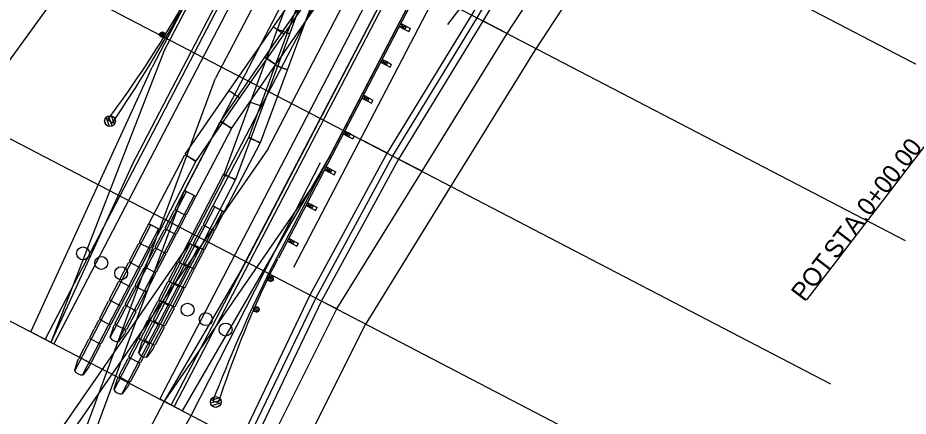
# Model space of a CAD drawing. Extents: x 2034057 to 2035954, y 247386 to 249135.
# Drawn here: x 2034166.1 to 2034303.8, y 247727.3 to 247789 of the extents above; entities that cross this region are included whole.
import ezdxf

# ---------------------------------------------------------------- set-up
doc = ezdxf.new("R2010")
doc.units = 0
for name, color, linetype in [('_CIVIL_CONSTRUCTION', 7, 'Continuous'), ('Default', 7, 'Continuous'), ('DR_X_Storm_Sewer', 7, 'Continuous'), ('DR_X_Text', 7, 'Continuous'), ('DV_X_Property_Line', 7, 'Continuous'), ('PV_X_Driveway', 7, 'Continuous'), ('RD_X_GR_Lt', 7, 'Continuous'), ('RS_Raster1', 7, 'Continuous'), ('RW_X_CL_100_Stations', 7, 'Continuous'), ('RW_X_Esmt_SH', 7, 'Continuous'), ('SC_Scratch1', 7, 'Continuous'), ('SN_X_Public', 7, 'Continuous'), ('SV_Control_Point', 7, 'Continuous'), ('SV_P_Mon_Cells_Set', 7, 'Continuous'), ('SV_X_Break_Lines', 7, 'Continuous'), ('XS_X_Ground_Line', 7, 'Continuous')]:
    doc.layers.add(name, color=color, linetype=linetype)

msp = doc.modelspace()

# ---------------------------------------------------------------- linework, layer by layer
at = {"layer": '_CIVIL_CONSTRUCTION'}
for p, q in [((2034285.21, 247856.53), (2034232.55, 247787.93)), ((2034340.74, 247813.92), (2034288.09, 247745.31))]:
    msp.add_line(p, q, dxfattribs=at)
at = {"layer": 'Default'}
for p, q in [((2034137.53, 247869), (2034314.92, 247776.64)), ((2034125.98, 247846.83), (2034303.38, 247754.47)), ((2034114.43, 247824.66), (2034291.83, 247732.29)), ((2034102.89, 247802.48), (2034280.28, 247710.12)), ((2034091.34, 247780.31), (2034268.74, 247687.94))]:
    msp.add_line(p, q, dxfattribs=at)
at = {"layer": 'DR_X_Storm_Sewer'}
for p, q in [((2034208.79, 247750.36), (2034247.98, 247825.63)), ((2034241.77, 247786.54), (2034238.03, 247788.49)), ((2034219.1, 247770.16), (2034223.2, 247768.03)), ((2034228.62, 247765.2), (2034224.97, 247767.1)), ((2034215.42, 247743.89), (2034213.05, 247745.12))]:
    msp.add_line(p, q, dxfattribs=at)
for points in [[(2034256.26, 247823.15), (2034236.29, 247789.47), (2034223.22, 247768.07), (2034211.27, 247746.04), (2034200.52, 247723.55), (2034200.47, 247723.49)], [(2034257.98, 247822.13), (2034238, 247788.44), (2034224.95, 247767.07), (2034213.06, 247745.13), (2034202.26, 247722.56)], [(2034228.62, 247765.2), (2034241.77, 247786.54), (2034255.56, 247807.55), (2034261.45, 247817.37)], [(2034204.23, 247721.53), (2034215.42, 247743.89), (2034228.62, 247765.2)]]:
    msp.add_lwpolyline(points, dxfattribs=at)
at = {"layer": 'DR_X_Text'}
msp.add_lwpolyline([(2034185.35, 247713.83), (2034192.91, 247727.42), (2034204.24, 247749.71), (2034212.91, 247766.55)], dxfattribs=at)
at = {"layer": 'DV_X_Property_Line'}
for p, q in [((2034235.31, 247874.38), (2034186.85, 247781.31)), ((2034262.59, 247860.18), (2034214.13, 247767.11)), ((2034168.07, 247740.36), (2034186.85, 247781.31)), ((2034191.57, 247728.12), (2034214.13, 247767.11)), ((2034168.07, 247740.36), (2034170.28, 247739.21)), ((2034189.8, 247729.05), (2034191.57, 247728.12))]:
    msp.add_line(p, q, dxfattribs=at)
at = {"layer": 'PV_X_Driveway'}
for p, q in [((2034183.71, 247766.07), (2034239.08, 247872.42)), ((2034247.06, 247868.27), (2034191.69, 247761.92)), ((2034183.71, 247766.07), (2034171.19, 247738.73)), ((2034191.69, 247761.92), (2034157.41, 247669.23)), ((2034184.77, 247737.07), (2034196.54, 247759.68)), ((2034197.72, 247759.06), (2034185.95, 247736.45)), ((2034194.78, 247757.02), (2034196.24, 247759.83)), ((2034198.02, 247758.91), (2034196.24, 247759.83)), ((2034196.56, 247756.1), (2034198.02, 247758.91)), ((2034193.24, 247754.07), (2034194.63, 247756.73)), ((2034194.85, 247756.8), (2034194.63, 247756.73)), ((2034194.78, 247757.02), (2034194.85, 247756.8)), ((2034196.33, 247756.03), (2034194.85, 247756.8)), ((2034195.02, 247753.14), (2034196.4, 247755.8)), ((2034196.56, 247756.1), (2034196.33, 247756.03)), ((2034196.33, 247756.03), (2034196.4, 247755.8)), ((2034191.7, 247751.11), (2034193.09, 247753.77)), ((2034193.31, 247753.84), (2034193.09, 247753.77)), ((2034193.24, 247754.07), (2034193.31, 247753.84)), ((2034194.79, 247753.07), (2034193.31, 247753.84)), ((2034193.48, 247750.19), (2034194.86, 247752.85)), ((2034195.02, 247753.14), (2034194.79, 247753.07)), ((2034194.79, 247753.07), (2034194.86, 247752.85)), ((2034190.16, 247748.15), (2034191.55, 247750.81)), ((2034191.77, 247750.88), (2034191.55, 247750.81)), ((2034191.7, 247751.11), (2034191.77, 247750.88)), ((2034193.25, 247750.11), (2034191.77, 247750.88)), ((2034191.94, 247747.23), (2034193.32, 247749.89)), ((2034193.48, 247750.19), (2034193.25, 247750.11)), ((2034193.25, 247750.11), (2034193.32, 247749.89)), ((2034190.16, 247748.15), (2034190.23, 247747.93)), ((2034188.62, 247745.2), (2034190.01, 247747.86)), ((2034190.23, 247747.93), (2034190.01, 247747.86)), ((2034191.71, 247747.16), (2034190.23, 247747.93)), ((2034190.4, 247744.27), (2034191.78, 247746.93)), ((2034191.94, 247747.23), (2034191.71, 247747.16)), ((2034191.71, 247747.16), (2034191.78, 247746.93)), ((2034187.08, 247742.24), (2034188.47, 247744.9)), ((2034188.69, 247744.97), (2034188.47, 247744.9)), ((2034188.62, 247745.2), (2034188.69, 247744.97)), ((2034190.17, 247744.2), (2034188.69, 247744.97)), ((2034190.24, 247743.98), (2034188.86, 247741.32)), ((2034190.4, 247744.27), (2034190.17, 247744.2)), ((2034190.17, 247744.2), (2034190.24, 247743.98)), ((2034185.55, 247739.28), (2034186.93, 247741.94)), ((2034187.16, 247742.01), (2034186.93, 247741.94)), ((2034187.08, 247742.24), (2034187.16, 247742.01)), ((2034188.63, 247741.24), (2034187.16, 247742.01)), ((2034188.86, 247741.32), (2034188.63, 247741.24)), ((2034188.63, 247741.24), (2034188.7, 247741.02)), ((2034188.7, 247741.02), (2034187.32, 247738.36)), ((2034185.19, 247738.6), (2034184.72, 247737.15)), ((2034185.19, 247738.6), (2034185.39, 247738.99)), ((2034185.62, 247739.06), (2034185.39, 247738.99)), ((2034185.55, 247739.28), (2034185.62, 247739.06)), ((2034187.09, 247738.29), (2034185.62, 247739.06)), ((2034187.32, 247738.36), (2034187.09, 247738.29)), ((2034186.96, 247737.68), (2034186.05, 247736.46)), ((2034187.17, 247738.06), (2034186.96, 247737.68)), ((2034187.09, 247738.29), (2034187.17, 247738.06))]:
    msp.add_line(p, q, dxfattribs=at)
for points in [[(2034207.78, 247780.92), (2034211.95, 247792.17), (2034210.07, 247792.87), (2034205.9, 247781.61)], [(2034203.61, 247769.67), (2034207.78, 247780.92), (2034205.9, 247781.61), (2034201.74, 247770.36)], [(2034198.02, 247758.91), (2034203.56, 247769.55), (2034201.79, 247770.47), (2034196.24, 247759.83)]]:
    msp.add_lwpolyline(points, close=True, dxfattribs=at)
for centre in [(2034176.16, 247752.49), (2034178.98, 247751.02), (2034182.06, 247749.42), (2034192.33, 247743.78), (2034195.15, 247742.31), (2034198.22, 247740.71)]:
    msp.add_circle(centre, 1, dxfattribs=at)
msp.add_arc((2034185.89, 247737.79), 1.34, 208.3199, 276.6713, dxfattribs=at)
at = {"layer": 'RD_X_GR_Lt'}
for p, q in [((2034204.76, 247768.61), (2034254.6, 247864.34)), ((2034212.74, 247764.45), (2034262.59, 247860.18)), ((2034204.76, 247768.61), (2034133.48, 247665.92)), ((2034212.74, 247764.45), (2034188.71, 247729.61)), ((2034180.38, 247739.46), (2034192.15, 247762.07)), ((2034190.39, 247759.41), (2034191.85, 247762.22)), ((2034193.63, 247761.3), (2034191.85, 247762.22)), ((2034193.33, 247761.45), (2034181.56, 247738.85)), ((2034192.16, 247758.49), (2034193.63, 247761.3)), ((2034188.85, 247756.46), (2034190.24, 247759.12)), ((2034190.46, 247759.19), (2034190.24, 247759.12)), ((2034190.39, 247759.41), (2034190.46, 247759.19)), ((2034191.94, 247758.42), (2034190.46, 247759.19)), ((2034190.62, 247755.53), (2034192.01, 247758.2)), ((2034192.16, 247758.49), (2034191.94, 247758.42)), ((2034191.94, 247758.42), (2034192.01, 247758.2)), ((2034188.85, 247756.46), (2034188.92, 247756.23)), ((2034187.31, 247753.5), (2034188.7, 247756.16)), ((2034188.92, 247756.23), (2034188.7, 247756.16)), ((2034190.4, 247755.46), (2034188.92, 247756.23)), ((2034189.09, 247752.58), (2034190.47, 247755.24)), ((2034190.62, 247755.53), (2034190.4, 247755.46)), ((2034190.4, 247755.46), (2034190.47, 247755.24)), ((2034187.31, 247753.5), (2034187.38, 247753.28)), ((2034185.77, 247750.54), (2034187.16, 247753.21)), ((2034187.38, 247753.28), (2034187.16, 247753.21)), ((2034188.86, 247752.51), (2034187.38, 247753.28)), ((2034187.55, 247749.62), (2034188.93, 247752.28)), ((2034189.09, 247752.58), (2034188.86, 247752.51)), ((2034188.86, 247752.51), (2034188.93, 247752.28)), ((2034184.23, 247747.59), (2034185.62, 247750.25)), ((2034185.84, 247750.32), (2034185.62, 247750.25)), ((2034185.77, 247750.54), (2034185.84, 247750.32)), ((2034187.32, 247749.55), (2034185.84, 247750.32)), ((2034187.55, 247749.62), (2034187.32, 247749.55)), ((2034187.32, 247749.55), (2034187.39, 247749.33)), ((2034186.01, 247746.66), (2034187.39, 247749.33)), ((2034182.69, 247744.63), (2034184.08, 247747.29)), ((2034184.3, 247747.36), (2034184.08, 247747.29)), ((2034184.23, 247747.59), (2034184.3, 247747.36)), ((2034185.78, 247746.59), (2034184.3, 247747.36)), ((2034186.01, 247746.66), (2034185.78, 247746.59)), ((2034185.78, 247746.59), (2034185.85, 247746.37)), ((2034185.85, 247746.37), (2034184.47, 247743.71)), ((2034181.15, 247741.68), (2034182.54, 247744.34)), ((2034182.76, 247744.41), (2034182.54, 247744.34)), ((2034182.69, 247744.63), (2034182.76, 247744.41)), ((2034184.24, 247743.64), (2034182.76, 247744.41)), ((2034184.31, 247743.41), (2034182.93, 247740.75)), ((2034184.47, 247743.71), (2034184.24, 247743.64)), ((2034184.24, 247743.64), (2034184.31, 247743.41)), ((2034180.8, 247740.99), (2034181, 247741.38)), ((2034181.22, 247741.45), (2034181, 247741.38)), ((2034181.15, 247741.68), (2034181.22, 247741.45)), ((2034182.7, 247740.68), (2034181.22, 247741.45)), ((2034180.8, 247740.99), (2034180.33, 247739.55)), ((2034182.57, 247740.07), (2034181.66, 247738.85)), ((2034182.77, 247740.46), (2034182.57, 247740.07)), ((2034182.93, 247740.75), (2034182.7, 247740.68)), ((2034182.7, 247740.68), (2034182.77, 247740.46))]:
    msp.add_line(p, q, dxfattribs=at)
for points in [[(2034212.76, 247791.57), (2034205.93, 247781.7), (2034204.29, 247782.84), (2034211.12, 247792.71)], [(2034205.93, 247781.7), (2034199.1, 247771.84), (2034197.46, 247772.97), (2034204.29, 247782.84)], [(2034199.17, 247771.94), (2034193.63, 247761.3), (2034191.85, 247762.22), (2034197.39, 247772.87)]]:
    msp.add_lwpolyline(points, close=True, dxfattribs=at)
msp.add_lwpolyline([(2034188.71, 247729.61), (2034177.8, 247708.67), (2034166.36, 247686.43), (2034157.41, 247669.23)], dxfattribs=at)
msp.add_arc((2034181.5, 247740.18), 1.34, 208.3199, 276.6713, dxfattribs=at)
at = {"layer": 'RS_Raster1'}
for p, q in [((2034188.68, 247783.74), (2034235.76, 247874.15)), ((2034243.74, 247870), (2034196.67, 247779.59)), ((2034206.26, 247787.17), (2034210.43, 247798.42)), ((2034208.14, 247786.48), (2034212.3, 247797.73)), ((2034202.09, 247775.92), (2034206.26, 247787.17)), ((2034206.26, 247787.17), (2034208.14, 247786.48)), ((2034206.26, 247787.17), (2034208.14, 247786.48)), ((2034203.97, 247775.22), (2034208.14, 247786.48)), ((2034188.68, 247783.74), (2034171.19, 247738.73)), ((2034151.87, 247658.6), (2034196.67, 247779.59)), ((2034197.92, 247764.66), (2034202.09, 247775.92)), ((2034202.09, 247775.92), (2034203.97, 247775.22)), ((2034202.09, 247775.92), (2034203.97, 247775.22)), ((2034199.8, 247763.97), (2034203.97, 247775.22)), ((2034192.43, 247754.14), (2034197.97, 247764.78)), ((2034197.92, 247764.66), (2034199.8, 247763.97)), ((2034197.97, 247764.78), (2034199.75, 247763.86)), ((2034194.21, 247753.21), (2034199.75, 247763.86)), ((2034180.96, 247731.37), (2034192.73, 247753.98)), ((2034190.97, 247751.33), (2034192.43, 247754.14)), ((2034192.43, 247754.14), (2034194.21, 247753.21)), ((2034194.21, 247753.21), (2034192.43, 247754.14)), ((2034193.91, 247753.37), (2034182.14, 247730.76)), ((2034192.74, 247750.4), (2034194.21, 247753.21)), ((2034189.43, 247748.37), (2034190.82, 247751.03)), ((2034191.04, 247751.1), (2034190.82, 247751.03)), ((2034190.97, 247751.33), (2034191.04, 247751.1)), ((2034192.52, 247750.33), (2034191.04, 247751.1)), ((2034191.21, 247747.45), (2034192.59, 247750.11)), ((2034192.74, 247750.4), (2034192.52, 247750.33)), ((2034192.52, 247750.33), (2034192.59, 247750.11)), ((2034187.89, 247745.41), (2034189.28, 247748.07)), ((2034189.5, 247748.15), (2034189.28, 247748.07)), ((2034189.43, 247748.37), (2034189.5, 247748.15)), ((2034190.98, 247747.38), (2034189.5, 247748.15)), ((2034189.67, 247744.49), (2034191.05, 247747.15)), ((2034191.21, 247747.45), (2034190.98, 247747.38)), ((2034190.98, 247747.38), (2034191.05, 247747.15)), ((2034187.89, 247745.41), (2034187.96, 247745.19)), ((2034186.35, 247742.46), (2034187.74, 247745.12)), ((2034187.96, 247745.19), (2034187.74, 247745.12)), ((2034189.44, 247744.42), (2034187.96, 247745.19)), ((2034188.13, 247741.53), (2034189.51, 247744.19)), ((2034189.67, 247744.49), (2034189.44, 247744.42)), ((2034189.44, 247744.42), (2034189.51, 247744.19)), ((2034184.81, 247739.5), (2034186.2, 247742.16)), ((2034186.42, 247742.23), (2034186.2, 247742.16)), ((2034186.35, 247742.46), (2034186.42, 247742.23)), ((2034187.9, 247741.46), (2034186.42, 247742.23)), ((2034186.59, 247738.58), (2034187.97, 247741.24)), ((2034188.13, 247741.53), (2034187.9, 247741.46)), ((2034187.9, 247741.46), (2034187.97, 247741.24)), ((2034183.27, 247736.54), (2034184.66, 247739.2)), ((2034184.88, 247739.28), (2034184.66, 247739.2)), ((2034184.81, 247739.5), (2034184.88, 247739.28)), ((2034186.36, 247738.51), (2034184.88, 247739.28)), ((2034186.59, 247738.58), (2034186.36, 247738.51)), ((2034186.36, 247738.51), (2034186.43, 247738.28)), ((2034186.43, 247738.28), (2034185.05, 247735.62)), ((2034181.73, 247733.59), (2034183.12, 247736.25)), ((2034183.34, 247736.32), (2034183.12, 247736.25)), ((2034183.27, 247736.54), (2034183.34, 247736.32)), ((2034184.82, 247735.55), (2034183.34, 247736.32)), ((2034185.05, 247735.62), (2034184.82, 247735.55)), ((2034184.89, 247735.32), (2034183.51, 247732.66)), ((2034184.82, 247735.55), (2034184.89, 247735.32)), ((2034181.38, 247732.9), (2034180.91, 247731.46)), ((2034181.38, 247732.9), (2034181.58, 247733.29)), ((2034181.81, 247733.36), (2034181.58, 247733.29)), ((2034181.73, 247733.59), (2034181.81, 247733.36)), ((2034183.28, 247732.59), (2034181.81, 247733.36)), ((2034183.15, 247731.98), (2034182.24, 247730.77)), ((2034183.35, 247732.37), (2034183.15, 247731.98)), ((2034183.51, 247732.66), (2034183.28, 247732.59)), ((2034183.28, 247732.59), (2034183.35, 247732.37))]:
    msp.add_line(p, q, dxfattribs=at)
msp.add_arc((2034182.08, 247732.09), 1.34, 208.3199, 276.6713, dxfattribs=at)
at = {"layer": 'RW_X_CL_100_Stations'}
msp.add_line((2034315.48, 247781.01), (2034288.09, 247745.31), dxfattribs=at)
at = {"layer": 'RW_X_Esmt_SH'}
for p, q in [((2034239.53, 247872.19), (2034170.28, 247739.21)), ((2034259.04, 247862.03), (2034189.8, 247729.05)), ((2034217.8, 247827.21), (2034171.62, 247738.51)), ((2034234.21, 247818.67), (2034188.02, 247729.97)), ((2034170.28, 247739.21), (2034171.62, 247738.51)), ((2034188.02, 247729.97), (2034189.8, 247729.05))]:
    msp.add_line(p, q, dxfattribs=at)
at = {"layer": 'SC_Scratch1'}
for p, q in [((2034251.06, 247866.19), (2034192.77, 247754.24)), ((2034200.75, 247750.08), (2034259.04, 247862.03)), ((2034205.62, 247787.57), (2034212.45, 247797.44)), ((2034207.27, 247786.43), (2034214.1, 247796.3)), ((2034198.79, 247777.7), (2034205.62, 247787.57)), ((2034205.62, 247787.57), (2034207.27, 247786.43)), ((2034205.62, 247787.57), (2034207.27, 247786.43)), ((2034200.44, 247776.57), (2034207.27, 247786.43)), ((2034191.97, 247767.84), (2034198.79, 247777.7)), ((2034198.79, 247777.7), (2034200.44, 247776.57)), ((2034198.79, 247777.7), (2034200.44, 247776.57)), ((2034193.61, 247766.7), (2034200.44, 247776.57)), ((2034186.36, 247757.09), (2034191.9, 247767.73)), ((2034191.9, 247767.73), (2034193.67, 247766.81)), ((2034191.97, 247767.84), (2034193.61, 247766.7)), ((2034188.13, 247756.16), (2034193.67, 247766.81)), ((2034174.88, 247734.32), (2034186.65, 247756.93)), ((2034187.84, 247756.32), (2034176.07, 247733.71)), ((2034184.9, 247754.28), (2034186.36, 247757.09)), ((2034186.36, 247757.09), (2034188.13, 247756.16)), ((2034188.13, 247756.16), (2034186.36, 247757.09)), ((2034186.67, 247753.35), (2034188.13, 247756.16)), ((2034138.55, 247675.74), (2034192.77, 247754.24)), ((2034183.36, 247751.32), (2034184.74, 247753.98)), ((2034184.97, 247754.05), (2034184.74, 247753.98)), ((2034184.9, 247754.28), (2034184.97, 247754.05)), ((2034186.45, 247753.28), (2034184.97, 247754.05)), ((2034185.13, 247750.4), (2034186.52, 247753.06)), ((2034186.67, 247753.35), (2034186.45, 247753.28)), ((2034186.45, 247753.28), (2034186.52, 247753.06)), ((2034181.82, 247748.36), (2034183.2, 247751.02)), ((2034183.43, 247751.1), (2034183.2, 247751.02)), ((2034183.36, 247751.32), (2034183.43, 247751.1)), ((2034184.91, 247750.33), (2034183.43, 247751.1)), ((2034183.59, 247747.44), (2034184.98, 247750.1)), ((2034185.13, 247750.4), (2034184.91, 247750.33)), ((2034184.91, 247750.33), (2034184.98, 247750.1)), ((2034200.75, 247750.08), (2034188.71, 247729.61)), ((2034180.28, 247745.41), (2034181.66, 247748.07)), ((2034181.89, 247748.14), (2034181.66, 247748.07)), ((2034181.82, 247748.36), (2034181.89, 247748.14)), ((2034183.37, 247747.37), (2034181.89, 247748.14)), ((2034182.05, 247744.48), (2034183.44, 247747.14)), ((2034183.59, 247747.44), (2034183.37, 247747.37)), ((2034183.37, 247747.37), (2034183.44, 247747.14)), ((2034180.28, 247745.41), (2034180.35, 247745.18)), ((2034178.74, 247742.45), (2034180.12, 247745.11)), ((2034180.35, 247745.18), (2034180.12, 247745.11)), ((2034181.83, 247744.41), (2034180.35, 247745.18)), ((2034180.51, 247741.53), (2034181.9, 247744.19)), ((2034182.05, 247744.48), (2034181.83, 247744.41)), ((2034181.83, 247744.41), (2034181.9, 247744.19)), ((2034177.2, 247739.49), (2034178.59, 247742.15)), ((2034178.81, 247742.23), (2034178.59, 247742.15)), ((2034178.74, 247742.45), (2034178.81, 247742.23)), ((2034180.29, 247741.46), (2034178.81, 247742.23)), ((2034180.36, 247741.23), (2034178.97, 247738.57)), ((2034180.51, 247741.53), (2034180.29, 247741.46)), ((2034180.29, 247741.46), (2034180.36, 247741.23)), ((2034175.66, 247736.54), (2034177.05, 247739.2)), ((2034177.27, 247739.27), (2034177.05, 247739.2)), ((2034177.2, 247739.49), (2034177.27, 247739.27)), ((2034178.75, 247738.5), (2034177.27, 247739.27)), ((2034178.97, 247738.57), (2034178.75, 247738.5)), ((2034178.75, 247738.5), (2034178.82, 247738.27)), ((2034178.82, 247738.27), (2034177.43, 247735.61)), ((2034175.31, 247735.86), (2034174.83, 247734.41)), ((2034175.31, 247735.86), (2034175.51, 247736.24)), ((2034175.73, 247736.31), (2034175.51, 247736.24)), ((2034175.66, 247736.54), (2034175.73, 247736.31)), ((2034177.21, 247735.54), (2034175.73, 247736.31)), ((2034177.43, 247735.61), (2034177.21, 247735.54)), ((2034177.08, 247734.93), (2034176.16, 247733.72)), ((2034177.28, 247735.32), (2034177.08, 247734.93)), ((2034177.21, 247735.54), (2034177.28, 247735.32))]:
    msp.add_line(p, q, dxfattribs=at)
msp.add_arc((2034176.01, 247735.04), 1.34, 208.3199, 276.6713, dxfattribs=at)
at = {"layer": 'SN_X_Public'}
for p, q in [((2034244.98, 247833.94), (2034190.24, 247728.81)), ((2034190.24, 247728.81), (2034188.71, 247729.61))]:
    msp.add_line(p, q, dxfattribs=at)
at = {"layer": 'SV_Control_Point'}
for p, q in [((2034206.22, 247751.92), (2034252.4, 247840.62)), ((2034206.44, 247751.81), (2034252.62, 247840.5)), ((2034225.97, 247787.16), (2034225.32, 247788.06)), ((2034225.09, 247787.62), (2034226.2, 247787.6)), ((2034225.97, 247787.16), (2034226.57, 247786.85)), ((2034226.2, 247787.6), (2034226.8, 247787.29)), ((2034226.57, 247786.85), (2034226.8, 247787.29)), ((2034223.09, 247781.61), (2034222.43, 247782.52)), ((2034222.2, 247782.08), (2034223.32, 247782.06)), ((2034223.09, 247781.61), (2034223.68, 247781.31)), ((2034223.32, 247782.06), (2034223.91, 247781.75)), ((2034223.68, 247781.31), (2034223.91, 247781.75)), ((2034220.2, 247776.07), (2034219.55, 247776.98)), ((2034219.31, 247776.53), (2034220.43, 247776.51)), ((2034220.2, 247776.07), (2034220.79, 247775.76)), ((2034220.43, 247776.51), (2034221.02, 247776.21)), ((2034220.79, 247775.76), (2034221.02, 247776.21)), ((2034217.31, 247770.53), (2034216.66, 247771.43)), ((2034216.43, 247770.99), (2034217.55, 247770.97)), ((2034217.31, 247770.53), (2034217.91, 247770.22)), ((2034217.55, 247770.97), (2034218.14, 247770.66)), ((2034217.91, 247770.22), (2034218.14, 247770.66)), ((2034214.43, 247764.98), (2034213.77, 247765.89)), ((2034213.54, 247765.44), (2034214.66, 247765.43)), ((2034214.43, 247764.98), (2034215.02, 247764.67)), ((2034214.66, 247765.43), (2034215.25, 247765.12)), ((2034215.02, 247764.67), (2034215.25, 247765.12)), ((2034210.66, 247759.9), (2034211.77, 247759.88)), ((2034211.54, 247759.44), (2034210.89, 247760.34)), ((2034211.54, 247759.44), (2034212.13, 247759.13)), ((2034211.77, 247759.88), (2034212.36, 247759.57)), ((2034212.13, 247759.13), (2034212.36, 247759.57)), ((2034207.77, 247754.36), (2034208.89, 247754.34)), ((2034208.66, 247753.9), (2034208, 247754.8)), ((2034208.66, 247753.9), (2034209.25, 247753.59)), ((2034208.89, 247754.34), (2034209.48, 247754.03)), ((2034209.25, 247753.59), (2034209.48, 247754.03)), ((2034204.65, 247748.9), (2034206.22, 247751.92)), ((2034204.84, 247748.8), (2034206.35, 247751.7)), ((2034197.07, 247729.36), (2034196.26, 247729.66))]:
    msp.add_line(p, q, dxfattribs=at)
for points in [[(2034226.2, 247787.6), (2034225.32, 247788.06), (2034225.09, 247787.62), (2034225.97, 247787.16)], [(2034223.32, 247782.06), (2034222.43, 247782.52), (2034222.2, 247782.08), (2034223.09, 247781.61)], [(2034220.43, 247776.51), (2034219.55, 247776.98), (2034219.31, 247776.53), (2034220.2, 247776.07)], [(2034217.55, 247770.97), (2034216.66, 247771.43), (2034216.43, 247770.99), (2034217.31, 247770.53)], [(2034214.66, 247765.43), (2034213.77, 247765.89), (2034213.54, 247765.44), (2034214.43, 247764.98)], [(2034211.77, 247759.88), (2034210.89, 247760.34), (2034210.66, 247759.9), (2034211.54, 247759.44)], [(2034208.89, 247754.34), (2034208, 247754.8), (2034207.77, 247754.36), (2034208.66, 247753.9)]]:
    msp.add_lwpolyline(points, close=True, dxfattribs=at)
for points in [[(2034204.77, 247748.49), (2034205.57, 247748.7)], [(2034204.79, 247748.71), (2034205.44, 247748.89)], [(2034204.86, 247748.29), (2034205.59, 247748.49)], [(2034205.12, 247748.15), (2034205.44, 247748.24)], [(2034202.58, 247743.75), (2034203.38, 247743.97)], [(2034202.6, 247743.97), (2034203.25, 247744.15)], [(2034202.67, 247743.56), (2034203.4, 247743.76)], [(2034202.93, 247743.41), (2034203.25, 247743.5)], [(2034195.91, 247729.79), (2034197.21, 247730.15)], [(2034195.87, 247729.35), (2034197.47, 247729.79)], [(2034196.05, 247728.97), (2034197.51, 247729.37)], [(2034196.57, 247728.68), (2034197.21, 247728.85)]]:
    msp.add_lwpolyline(points, dxfattribs=at)
for centre, radius in [((2034205.18, 247748.56), 0.417), ((2034202.99, 247743.82), 0.417), ((2034196.69, 247729.5), 0.833)]:
    msp.add_circle(centre, radius, dxfattribs=at)
for centre, radius, start, end in [((2034410.24, 247647.8), 229.11, 153.8126, 159.0644), ((2034347, 247680.74), 157.61, 154.4148, 162.0331)]:
    msp.add_arc(centre, radius, start, end, dxfattribs=at)
at = {"layer": 'SV_P_Mon_Cells_Set'}
msp.add_line((2034179.99, 247773.2), (2034180.71, 247772.71), dxfattribs=at)
for points in [[(2034188.41, 247785.93), (2034188.16, 247786.64)], [(2034188.62, 247785.96), (2034188.34, 247786.74)], [(2034188.79, 247786.1), (2034188.57, 247786.74)], [(2034188.15, 247786.06), (2034188.04, 247786.37)], [(2034179.72, 247772.4), (2034179.5, 247773.02)], [(2034180.26, 247772.14), (2034179.75, 247773.57)], [(2034180.67, 247772.21), (2034180.11, 247773.78)], [(2034181.01, 247772.5), (2034180.56, 247773.77)]]:
    msp.add_lwpolyline(points, dxfattribs=at)
for centre, radius in [((2034188.45, 247786.34), 0.417), ((2034180.33, 247772.97), 0.833)]:
    msp.add_circle(centre, radius, dxfattribs=at)
for centre, radius, start, end in [((2034054.18, 247868.15), 157.61, 322.9585, 330.5768), ((2033990.93, 247901.06), 229.11, 325.9272, 331.179)]:
    msp.add_arc(centre, radius, start, end, dxfattribs=at)
at = {"layer": 'SV_X_Break_Lines'}
msp.add_lwpolyline([(2034191.46, 247710.48), (2034201.37, 247723.02), (2034212.16, 247745.59), (2034224.08, 247767.57), (2034237.15, 247788.95), (2034257.12, 247822.64)], dxfattribs=at)
at = {"layer": 'XS_X_Ground_Line'}
for points in [[(2034265.59, 247814.55), (2034259.8, 247804.89), (2034245.99, 247783.86), (2034232.88, 247762.57)], [(2034158.38, 247773.59), (2034173.22, 247794.05), (2034188.39, 247813.42)], [(2034232.88, 247762.57), (2034219.79, 247741.45), (2034209.54, 247720.98)]]:
    msp.add_lwpolyline(points, dxfattribs=at)

# ---------------------------------------------------------------- texts
at = {"layer": 'RW_X_CL_100_Stations'}
for s, p in [('0+00.00', (2034297.85, 247758.1)), (' STA. ', (2034292.09, 247750.6)), ('POT', (2034287.71, 247744.89))]:
    msp.add_text(s, height=2.8, rotation=52.4956, dxfattribs=at).set_placement(p)

doc.saveas('drawing.dxf')
